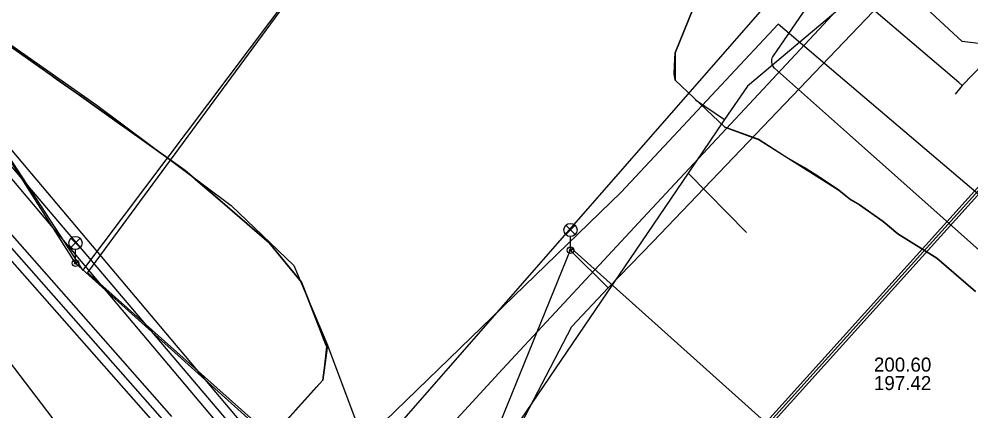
# Model space of a CAD drawing. Extents: x -598932 to -598196, y -1162210 to -1161504.
# Drawn here: x -598627.1 to -598572.9, y -1161751.5 to -1161729.1 of the extents above; entities that cross this region are included whole.
import ezdxf

# ---------------------------------------------------------------- set-up
doc = ezdxf.new("R2010")
doc.units = 0
for name, color, linetype in [('Vrstva 1', 7, 'Continuous'), ('Vrstva 10', 7, 'Continuous'), ('Vrstva 12', 7, 'Continuous'), ('Vrstva 13', 7, 'Continuous'), ('Vrstva 14', 7, 'Continuous'), ('Vrstva 16', 7, 'Continuous'), ('Vrstva 33', 7, 'Continuous'), ('Vrstva 4', 7, 'Continuous'), ('Vrstva 42', 7, 'Continuous'), ('Vrstva 53', 7, 'Continuous'), ('Vrstva 54', 7, 'Continuous'), ('Vrstva 55', 7, 'Continuous'), ('Vrstva 58', 7, 'Continuous'), ('Vrstva 9', 7, 'Continuous')]:
    doc.layers.add(name, color=color, linetype=linetype)

msp = doc.modelspace()

# ---------------------------------------------------------------- linework, layer by layer
at = {"layer": 'Vrstva 1'}
msp.add_line((-598585.694, -1161741.289), (-598589.015, -1161737.903), dxfattribs=at)
at = {"layer": 'Vrstva 10'}
for p, q in [((-598648.42, -1161711.89), (-598612.32, -1161754.71)), ((-598648.42, -1161711.89), (-598612.32, -1161754.71)), ((-598649.44, -1161712.32), (-598613.14, -1161755.36)), ((-598649.44, -1161712.32), (-598613.14, -1161755.36)), ((-598638.16, -1161729.41), (-598618.46, -1161751.78)), ((-598638.16, -1161729.41), (-598618.46, -1161751.78)), ((-598639.01, -1161729.96), (-598619.23, -1161752.41)), ((-598639.01, -1161729.96), (-598619.23, -1161752.41))]:
    msp.add_line(p, q, dxfattribs=at)
at = {"layer": 'Vrstva 12'}
msp.add_line((-598611.21, -1161756.79), (-598644.24, -1161717.96), dxfattribs=at)
for points in [[(-598617.73, -1161753.57), (-598613.29, -1161752.78), (-598610.76, -1161755.12), (-598608.27, -1161755.41), (-598576.7, -1161719.3), (-598550.29, -1161690.77), (-598547.14, -1161687.36)], [(-598639.8, -1161728.29), (-598638.6, -1161729.7), (-598618.85, -1161752.1)]]:
    msp.add_lwpolyline(points, dxfattribs=at)
at = {"layer": 'Vrstva 13'}
msp.add_lwpolyline([(-598555.27, -1161753.75), (-598583.9, -1161729.43), (-598592.85, -1161739), (-598611.21, -1161756.79)], dxfattribs=at)
at = {"layer": 'Vrstva 14'}
for p, q in [((-598573.604, -1161732.736), (-598573.404, -1161732.925)), ((-598573.404, -1161732.925), (-598573.557, -1161733.106)), ((-598573.557, -1161733.106), (-598573.814, -1161733.409))]:
    msp.add_line(p, q, dxfattribs=at)
for points in [[(-598573.404, -1161732.925), (-598571.604, -1161731.052), (-598554.514, -1161713.376), (-598533.774, -1161691.098), (-598513.523, -1161668.723), (-598504.735, -1161659.069), (-598494, -1161647.223), (-598480.574, -1161632.154), (-598477.858, -1161629.221), (-598469.826, -1161620.401), (-598456.055, -1161605.679), (-598446.117, -1161594.93), (-598428.638, -1161575.491)], [(-598449.055, -1161597.092), (-598451.08, -1161599.354), (-598469.948, -1161619.476), (-598481.318, -1161632.069), (-598500.359, -1161653.156), (-598508.903, -1161662.52), (-598516.704, -1161671.085), (-598523.517, -1161678.934), (-598531.97, -1161688.321), (-598542.658, -1161699.746), (-598544.581, -1161701.802), (-598554.215, -1161711.962), (-598572.329, -1161730.54), (-598573.411, -1161730.417), (-598574.926, -1161728.994), (-598576.936, -1161727.101), (-598579.192, -1161727.23), (-598579.92, -1161727.954)], [(-598573.604, -1161732.736), (-598579.575, -1161727.644), (-598580.215, -1161727.105), (-598580.492, -1161727.456)], [(-598714.198, -1161898.74), (-598714.06, -1161898.556), (-598710.961, -1161889.776), (-598709.348, -1161885.209), (-598692.94, -1161864.74), (-598688.776, -1161860.738), (-598685, -1161855.44), (-598662.12, -1161826.49), (-598647.66, -1161808.72), (-598629.293, -1161785.959), (-598621.98, -1161776.96), (-598617.208, -1161768.282), (-598616.2, -1161767.15), (-598599.603, -1161749.072), (-598591.333, -1161740.194), (-598580.26, -1161728.311)]]:
    msp.add_lwpolyline(points, dxfattribs=at)
at = {"layer": 'Vrstva 16'}
for points in [[(-598584.21, -1161731.29), (-598584.25, -1161731.36), (-598584.27, -1161731.44), (-598584.28, -1161731.52), (-598584.28, -1161731.6), (-598584.26, -1161731.69), (-598584.25, -1161731.73), (-598584.21, -1161731.8), (-598584.14, -1161731.9), (-598584.11, -1161731.93), (-598579.83, -1161735.72), (-598571.74, -1161742.92), (-598560.67, -1161752.75), (-598556.13, -1161747.95), (-598548.8, -1161739.92), (-598547.35, -1161738.33), (-598536.23, -1161726.33), (-598530.7, -1161720.33), (-598528.8, -1161718.28), (-598523.82, -1161712.94), (-598516.92, -1161705.5), (-598511.95, -1161700.1), (-598506.77, -1161694.48)], [(-598581.16, -1161725.62), (-598581.38, -1161727.15), (-598584.21, -1161731.29)]]:
    msp.add_lwpolyline(points, dxfattribs=at)
at = {"layer": 'Vrstva 33'}
for p, q in [((-598595.997, -1161740.883), (-598595.467, -1161741.413)), ((-598595.997, -1161741.413), (-598595.467, -1161740.883)), ((-598624.201, -1161741.624), (-598623.671, -1161742.154)), ((-598624.201, -1161742.154), (-598623.671, -1161741.624)), ((-598595.732, -1161742.298), (-598595.732, -1161741.523)), ((-598623.936, -1161743.039), (-598623.936, -1161742.264))]:
    msp.add_line(p, q, dxfattribs=at)
for centre, radius in [((-598595.732, -1161741.148), 0.375), ((-598623.936, -1161741.889), 0.375), ((-598595.732, -1161742.298), 0.19), ((-598595.732, -1161742.298), 0.05), ((-598623.936, -1161743.039), 0.19), ((-598623.936, -1161743.039), 0.05)]:
    msp.add_circle(centre, radius, dxfattribs=at)
at = {"layer": 'Vrstva 42'}
for points in [[(-598482.625, -1161640.144), (-598482.467, -1161640.638), (-598493.794, -1161653.11), (-598495.271, -1161654.682), (-598509.79, -1161670.452), (-598509.789, -1161670.451), (-598514.544, -1161675.66), (-598514.586, -1161675.706), (-598563.469, -1161729.131), (-598604.648, -1161774.799), (-598616.464, -1161788.466), (-598628.603, -1161803.794)], [(-598628.837, -1161803.606), (-598616.696, -1161788.274), (-598604.872, -1161774.601), (-598563.691, -1161728.929), (-598514.958, -1161675.668), (-598514.766, -1161675.458), (-598510.011, -1161670.249), (-598510.01, -1161670.248), (-598495.509, -1161654.498), (-598494.886, -1161653.538)], [(-598628.837, -1161803.606), (-598616.696, -1161788.274), (-598604.872, -1161774.601), (-598563.691, -1161728.929), (-598514.958, -1161675.668), (-598514.766, -1161675.458), (-598510.011, -1161670.249), (-598510.01, -1161670.248), (-598495.509, -1161654.498), (-598494.886, -1161653.538)], [(-598722.434, -1161887.506), (-598721.303, -1161887.465), (-598711.981, -1161877.933), (-598701.016, -1161865.728), (-598698.292, -1161862.397), (-598697.293, -1161861.83), (-598689.452, -1161859.77), (-598688.12, -1161859.789), (-598687.331, -1161860.531), (-598681.484, -1161865.606), (-598680.195, -1161866.255), (-598678.811, -1161865.236), (-598675.692, -1161860.773), (-598673.236, -1161858.028), (-598665.054, -1161848.125), (-598640.034, -1161817.645), (-598628.603, -1161803.794), (-598616.464, -1161788.466), (-598604.648, -1161774.799), (-598563.469, -1161729.131), (-598514.586, -1161675.706), (-598514.881, -1161675.495)], [(-598514.841, -1161675.57), (-598514.772, -1161675.687), (-598563.58, -1161729.03), (-598604.76, -1161774.7), (-598616.58, -1161788.37), (-598628.72, -1161803.7), (-598640.15, -1161817.55), (-598650.17, -1161829.78), (-598665.17, -1161848.03), (-598673.35, -1161857.93), (-598675.81, -1161860.68), (-598678.92, -1161865.13), (-598680.21, -1161866.08), (-598681.4, -1161865.48), (-598687.23, -1161860.42), (-598688.06, -1161859.64), (-598689.47, -1161859.62), (-598697.35, -1161861.69), (-598698.39, -1161862.28), (-598701.13, -1161865.63), (-598712.09, -1161877.83), (-598721.41, -1161887.36)], [(-598572.66, -1161744.66), (-598574.86, -1161742.76), (-598577.08, -1161741.36), (-598577.92, -1161740.67), (-598579.26, -1161739.71), (-598579.81, -1161739.4), (-598580.43, -1161738.88), (-598581.6, -1161738.11), (-598582.42, -1161737.59), (-598583.53, -1161736.94), (-598585.03, -1161735.97), (-598586.94, -1161735.29), (-598589.77, -1161732.62), (-598589.83, -1161732.26), (-598589.79, -1161731.39), (-598589.77, -1161731.05), (-598588.73, -1161728.53)]]:
    msp.add_lwpolyline(points, dxfattribs=at)
at = {"layer": 'Vrstva 53'}
for points in [[(-598631.008, -1161728.217), (-598622.71, -1161734.03), (-598615.07, -1161739.76), (-598611.49, -1161743.17), (-598609.61, -1161747.61)], [(-598609.61, -1161747.61), (-598609.84, -1161749.7), (-598609.841, -1161749.701)], [(-598609.61, -1161747.61), (-598607.64, -1161752.88), (-598606.87, -1161755.71), (-598605.97, -1161758.94), (-598603.23, -1161774.02), (-598602.46, -1161776.53), (-598601.52, -1161779.31), (-598598.86, -1161784.84), (-598597.77, -1161787.35), (-598596.71, -1161790.67), (-598595.79, -1161793.54), (-598594.83, -1161796.22), (-598593.94, -1161799.41), (-598592.99, -1161801.85), (-598591.22, -1161806.87), (-598589.7, -1161809.75), (-598588.76, -1161814.1), (-598588.73, -1161814.4)], [(-598609.841, -1161749.701), (-598612.07, -1161752.18), (-598612.85, -1161753.03), (-598613.52, -1161753.62), (-598623.35, -1161763.72), (-598623.69, -1161765.36), (-598623.39, -1161766.52), (-598623.11, -1161769.13), (-598622.73, -1161770.39), (-598622.65, -1161771.79), (-598625.03, -1161775.74), (-598626.92, -1161777.34), (-598629.01, -1161780.33), (-598632.04, -1161785.05), (-598632.43, -1161785.95), (-598634.19, -1161788.81), (-598640.81, -1161797.29)]]:
    msp.add_lwpolyline(points, dxfattribs=at)
at = {"layer": 'Vrstva 54'}
msp.add_line((-598568.721, -1161766.31), (-598595.679, -1161742.213), dxfattribs=at)
msp.add_lwpolyline([(-598687.821, -1161859.742), (-598647.718, -1161830.151), (-598630.44, -1161809.067), (-598615.881, -1161791.862), (-598595.724, -1161742.271)], dxfattribs=at)
at = {"layer": 'Vrstva 55'}
for points in [[(-598687.9, -1161859.88), (-598687.665, -1161860.067), (-598686.34, -1161858.55), (-598665.36, -1161832.2), (-598647.88, -1161811.69), (-598632.26, -1161792.34), (-598620.6, -1161778.58), (-598617.8, -1161769.72), (-598610.34, -1161759), (-598610.34, -1161755.27), (-598623.936, -1161743.039), (-598634.82, -1161725.89), (-598648.11, -1161713.3), (-598648.437, -1161712.771), (-598653, -1161709.34), (-598656.27, -1161705.61), (-598668.62, -1161681.83), (-598671.66, -1161674.83), (-598683.11, -1161642.61), (-598670.09, -1161637.1), (-598667.406, -1161636.169), (-598667.557, -1161635.626)], [(-598635.02, -1161725.8), (-598623.513, -1161743.463), (-598608.12, -1161722.98), (-598608.22, -1161717.163), (-598608.12, -1161722.98), (-598623.249, -1161743.568), (-598610.78, -1161754.69), (-598601.71, -1161758.3), (-598595.65, -1161746.64), (-598593.576, -1161744.441), (-598595.719, -1161742.325), (-598593.576, -1161744.441), (-598591.036, -1161741.822), (-598575.14, -1161725.19), (-598564.458, -1161715.417), (-598553.451, -1161703.881), (-598547.789, -1161697.531), (-598546.625, -1161695.044), (-598548.56, -1161692.55), (-598559.49, -1161681.15), (-598556.019, -1161677.263), (-598556.805, -1161676.476)]]:
    msp.add_lwpolyline(points, dxfattribs=at)
at = {"layer": 'Vrstva 58'}
for p, q in [((-598623.725, -1161733.467), (-598627.64, -1161730.69)), ((-598627.64, -1161730.69), (-598625.537, -1161732.182)), ((-598625.21, -1161732.413), (-598623.712, -1161733.476)), ((-598619.797, -1161736.253), (-598623.712, -1161733.476)), ((-598623.712, -1161733.476), (-598621.296, -1161735.19)), ((-598621.282, -1161735.2), (-598619.471, -1161736.485)), ((-598617.68, -1161737.76), (-598619.471, -1161736.485)), ((-598619.471, -1161736.485), (-598617.68, -1161737.76)), ((-598615.708, -1161739.456), (-598617.68, -1161737.76)), ((-598617.68, -1161737.76), (-598617.392, -1161738.008)), ((-598617.088, -1161738.269), (-598615.696, -1161739.467)), ((-598612.89, -1161741.88), (-598615.696, -1161739.467)), ((-598615.696, -1161739.467), (-598613.449, -1161741.399)), ((-598613.437, -1161741.409), (-598612.89, -1161741.88)), ((-598612.194, -1161742.731), (-598612.89, -1161741.88)), ((-598612.89, -1161741.88), (-598611.05, -1161744.13)), ((-598611.05, -1161744.13), (-598611.941, -1161743.041)), ((-598609.821, -1161747.292), (-598611.05, -1161744.13)), ((-598611.05, -1161744.13), (-598610.626, -1161745.222)), ((-598610.481, -1161745.595), (-598609.821, -1161747.292)), ((-598609.821, -1161747.292), (-598609.6, -1161747.86)), ((-598609.6, -1161747.86), (-598609.815, -1161747.307)), ((-598609.84, -1161749.7), (-598609.6, -1161747.86)), ((-598609.6, -1161747.86), (-598609.84, -1161749.7)), ((-598611.417, -1161751.444), (-598609.84, -1161749.7)), ((-598609.84, -1161749.7), (-598610.185, -1161750.081)), ((-598610.196, -1161750.093), (-598612.85, -1161753.03))]:
    msp.add_line(p, q, dxfattribs=at)
for points in [[(-598586.79, -1161723.48), (-598587.41, -1161726.16), (-598588.73, -1161728.53), (-598589.77, -1161731.05), (-598589.77, -1161732.62), (-598586.94, -1161735.29), (-598584.97, -1161736.01), (-598580.43, -1161738.88), (-598579.76, -1161739.43), (-598579.26, -1161739.71), (-598577.92, -1161740.67), (-598577.08, -1161741.36), (-598574.86, -1161742.76), (-598572.66, -1161744.66)], [(-598623.69, -1161765.36), (-598623.26, -1161763.82), (-598613.35, -1161753.86), (-598612.85, -1161753.03), (-598612.07, -1161752.18), (-598609.84, -1161749.7), (-598609.6, -1161747.86), (-598611.05, -1161744.13), (-598612.89, -1161741.88), (-598617.68, -1161737.76), (-598618.91, -1161736.88), (-598619.66, -1161736.35), (-598631.7, -1161727.81)], [(-598623.69, -1161765.36), (-598623.35, -1161763.72), (-598613.52, -1161753.62), (-598612.85, -1161753.03), (-598612.07, -1161752.18), (-598609.84, -1161749.7), (-598609.6, -1161747.86), (-598611.05, -1161744.13), (-598612.89, -1161741.88), (-598617.68, -1161737.76), (-598618.91, -1161736.88), (-598619.66, -1161736.35), (-598631.7, -1161727.81)], [(-598628.535, -1161779.651), (-598626.92, -1161777.34), (-598625.408, -1161776.06), (-598625.03, -1161775.74), (-598622.65, -1161771.79), (-598622.73, -1161770.39), (-598623.11, -1161769.13), (-598623.39, -1161766.52), (-598623.69, -1161765.36), (-598623.35, -1161763.72), (-598613.52, -1161753.62), (-598612.85, -1161753.03), (-598609.84, -1161749.7), (-598609.6, -1161747.86), (-598611.05, -1161744.13), (-598612.89, -1161741.88), (-598615.696, -1161739.467), (-598617.68, -1161737.76), (-598619.66, -1161736.35), (-598631.7, -1161727.81)], [(-598572.66, -1161744.66), (-598574.86, -1161742.76), (-598577.08, -1161741.36), (-598577.92, -1161740.67), (-598579.26, -1161739.71), (-598579.81, -1161739.4), (-598580.43, -1161738.88), (-598581.6, -1161738.11), (-598582.42, -1161737.59), (-598583.53, -1161736.94), (-598585.03, -1161735.97), (-598586.94, -1161735.29), (-598589.77, -1161732.62), (-598589.83, -1161732.26), (-598589.79, -1161731.39), (-598589.77, -1161731.05), (-598588.73, -1161728.53)], [(-598627.64, -1161730.69), (-598623.712, -1161733.476), (-598619.471, -1161736.485), (-598617.68, -1161737.76), (-598615.696, -1161739.467), (-598612.89, -1161741.88), (-598611.05, -1161744.13), (-598609.821, -1161747.292), (-598609.6, -1161747.86), (-598609.84, -1161749.7), (-598612.85, -1161753.03)]]:
    msp.add_lwpolyline(points, dxfattribs=at)
at = {"layer": 'Vrstva 9'}
for p, q in [((-598588.597, -1161733.736), (-598586.944, -1161734.861)), ((-598632.98, -1161741.74), (-598613.88, -1161766.79))]:
    msp.add_line(p, q, dxfattribs=at)
for points in [[(-598545.587, -1161699.229), (-598555.907, -1161707.907), (-598561.598, -1161712.701), (-598565.921, -1161716.347), (-598585.65, -1161732.96)], [(-598585.65, -1161732.96), (-598586.944, -1161734.861), (-598589.015, -1161737.903), (-598599.59, -1161753.44)]]:
    msp.add_lwpolyline(points, dxfattribs=at)

# ---------------------------------------------------------------- texts
at = {"layer": 'Vrstva 4'}
for s, p in [('200.60', (-598578.441, -1161749.221)), ('197.42', (-598578.441, -1161750.271))]:
    msp.add_text(s, height=0.8, dxfattribs=at).set_placement(p)

doc.saveas('drawing.dxf')
